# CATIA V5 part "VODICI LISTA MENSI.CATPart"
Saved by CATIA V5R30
Part number: VODICI LISTA MENSI
Bounding box of the stored display mesh (mm): x -35.5 to 35.5, y 0 to 11, z -6.5 to 9.5
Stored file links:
  C:\Users\ondra\Desktop\PŘÍLOHA P III\CATIA\VODICI LISTA MENSI.CATPart
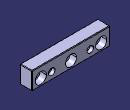
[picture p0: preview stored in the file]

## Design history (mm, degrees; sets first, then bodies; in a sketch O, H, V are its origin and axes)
Set1
  DatumSurface1 to DatumSurface43 "Z1850/16"
  Plane1: type Tangent, Support DatumSurface17, RefPoint vertex [face of DatumSurface16]
  Plane2: type Tangent, Support DatumSurface23, RefPoint vertex [face of DatumSurface11]
  Plane3: type Tangent, Support DatumSurface13, RefPoint vertex [face of DatumSurface13]
  Plane4: type Tangent, Support DatumSurface20, RefPoint vertex [face of DatumSurface18]
  Point1: type OnSurface, Support DatumSurface40, Length 0, Direction edge of DatumSurface41
  Plane5: type Tangent, Support DatumSurface40, RefPoint Point1
  Plane6: type Tangent, Support DatumSurface27, RefPoint vertex [face of DatumSurface14]
  Plane7: type Offset, RefPlane Plane6, Offset 1.5, reversed
  Join1: Elements (DatumSurface1; DatumSurface2; DatumSurface3; DatumSurface4; DatumSurface5; DatumSurface6; DatumSurface7; DatumSurface8; DatumSurface9; DatumSurface10; DatumSurface11; DatumSurface12; DatumSurface13; DatumSurface14; DatumSurface15; DatumSurface16; DatumSurface17; DatumSurface18; DatumSurface19; DatumSurface20; DatumSurface21; DatumSurface22; DatumSurface23; DatumSurface24; DatumSurface25; DatumSurface26; DatumSurface27; DatumSurface28; DatumSurface29; DatumSurface30; DatumSurface31; DatumSurface32; DatumSurface33; DatumSurface34; DatumSurface35; DatumSurface36; DatumSurface37; DatumSurface38; DatumSurface39; DatumSurface40; DatumSurface41; DatumSurface42; DatumSurface43)
Body1 (main body)
  CloseSurface1: CloseElement Join1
